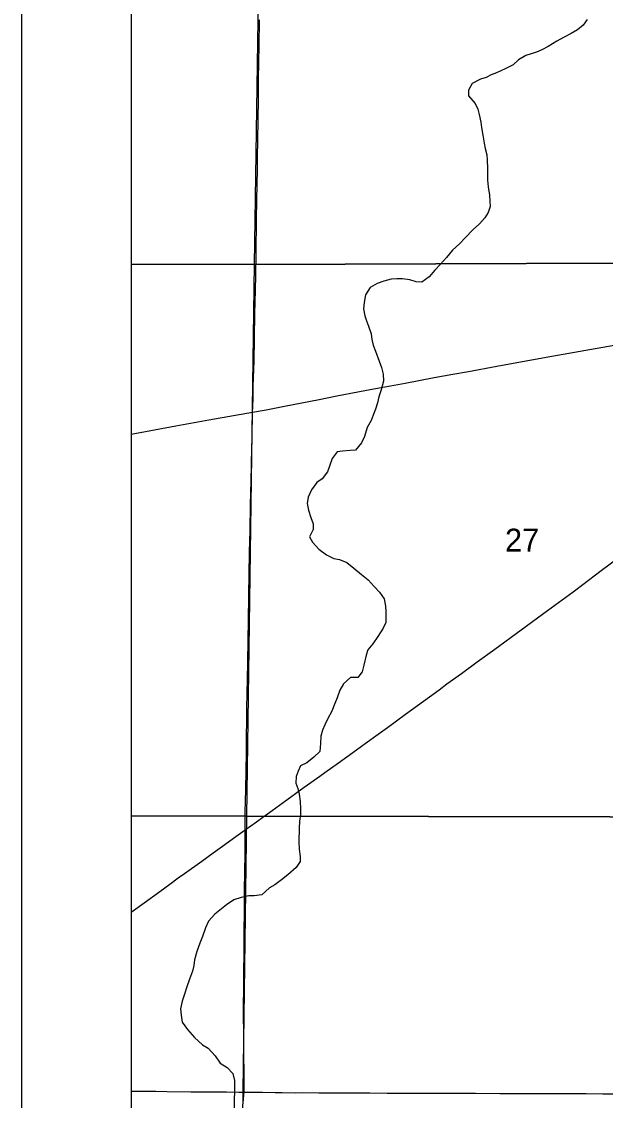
# Model space of a CAD drawing. Extents: x 0 to 34, y 0 to 22.
# Drawn here: x 2 to 2.532, y 14.978 to 15.961 of the extents above; entities that cross this region are included whole.
import ezdxf

# ---------------------------------------------------------------- set-up
doc = ezdxf.new("R2010")
doc.units = 0
for name, color, linetype in [('GM_X_Corporation', 7, 'Continuous'), ('GM_X_County_Road', 7, 'Continuous'), ('GM_X_Minor_River', 7, 'Continuous'), ('GM_X_Section_Text', 7, 'Continuous'), ('GM_X_Township_Road', 7, 'Continuous'), ('GM_X_US_Route', 7, 'Continuous'), ('SH_Data', 7, 'Continuous')]:
    doc.layers.add(name, color=color, linetype=linetype)

msp = doc.modelspace()

# ---------------------------------------------------------------- linework, layer by layer
at = {"layer": 'GM_X_Corporation'}
for points in [[(2.1, 20.71973), (2.1, 14.1), (8.9, 14.1), (8.9, 20.77204)], [(2.1, 17.73189), (2.1, 14.73602)]]:
    msp.add_lwpolyline(points, dxfattribs=at)
for points in [[(2.1, 16.24448), (2.1, 15.73976), (2.21216, 15.73952), (2.21995, 16.24572)], [(2.21995, 16.24572), (2.71086, 16.24467), (2.70763, 15.74147), (2.21216, 15.73952)], [(2.1, 15.73976), (2.1, 15.23741), (2.20515, 15.23711), (2.21216, 15.73952)], [(2.70763, 15.74147), (2.70155, 15.23601), (2.20515, 15.23711), (2.21216, 15.73952)], [(2.1, 15.23741), (2.1, 14.7363), (2.19853, 14.73564), (2.20515, 15.23711)], [(2.20515, 15.23711), (2.70155, 15.23601), (2.70022, 14.73337), (2.69643, 14.7334), (2.21255, 14.73573), (2.19853, 14.73564)]]:
    msp.add_lwpolyline(points, close=True, dxfattribs=at)
at = {"layer": 'GM_X_County_Road'}
for points in [[(2.20385, 15.22457), (2.21393, 15.23188), (2.21974, 15.23604), (2.22831, 15.24222), (2.23491, 15.24688), (2.23839, 15.24949), (2.25753, 15.2633), (2.27169, 15.27342), (2.27644, 15.27691), (2.2889, 15.28559), (2.30175, 15.29487), (2.30972, 15.30079), (2.31302, 15.30312), (2.32486, 15.31165), (2.33344, 15.31782), (2.34996, 15.32998), (2.36078, 15.33781), (2.37183, 15.34586), (2.38036, 15.35211), (2.38761, 15.35745), (2.40097, 15.36709), (2.41526, 15.37756), (2.43112, 15.38903), (2.4793, 15.42425), (2.50256, 15.4414), (2.51127, 15.44793), (2.52811, 15.46069), (2.54319, 15.47219)], [(2.1, 15.14939), (2.11167, 15.15801), (2.12594, 15.1685), (2.13502, 15.17502), (2.14282, 15.18067), (2.14834, 15.18471), (2.1643, 15.19604), (2.17461, 15.20353), (2.18319, 15.20969), (2.19531, 15.21839), (2.20385, 15.22457)], [(2.1, 14.98659), (2.10663, 14.98655), (2.12248, 14.98637), (2.13242, 14.98625), (2.15416, 14.986), (2.1868, 14.98575), (2.19798, 14.98562), (2.20275, 14.98559)], [(2.20275, 14.98559), (2.21104, 14.98554), (2.21943, 14.98547), (2.23122, 14.98527), (2.23743, 14.98517), (2.24955, 14.98507), (2.25638, 14.9851), (2.27099, 14.98505), (2.29119, 14.98505), (2.30456, 14.98495), (2.3173, 14.98487), (2.33314, 14.98463), (2.3434, 14.98465), (2.35303, 14.98462), (2.38815, 14.98462), (2.41364, 14.98451), (2.4357, 14.98438), (2.46492, 14.98446), (2.47797, 14.98431), (2.49195, 14.98433), (2.50159, 14.98436), (2.51433, 14.9843), (2.52955, 14.98417), (2.56374, 14.98414)]]:
    msp.add_lwpolyline(points, dxfattribs=at)
at = {"layer": 'GM_X_Minor_River'}
for points in [[(2.51541, 15.9629), (2.51158, 15.95762), (2.50643, 15.95348), (2.5009, 15.95011), (2.49367, 15.94656), (2.48776, 15.94319), (2.47975, 15.93812), (2.47404, 15.93513), (2.46909, 15.93308), (2.46434, 15.9316), (2.45939, 15.92993), (2.45273, 15.92618), (2.44795, 15.92166), (2.44052, 15.91773), (2.43272, 15.91419), (2.42796, 15.91251), (2.4232, 15.91008), (2.41807, 15.90841), (2.41064, 15.90448), (2.40718, 15.89844), (2.40733, 15.89312), (2.41316, 15.88625), (2.41559, 15.88111), (2.41707, 15.87616), (2.41854, 15.86932), (2.41908, 15.86457), (2.42016, 15.85755), (2.42144, 15.85014), (2.42235, 15.8452), (2.42402, 15.83949), (2.42436, 15.83456), (2.42469, 15.82696), (2.42465, 15.82184), (2.42442, 15.81653), (2.42513, 15.81026), (2.42622, 15.80266), (2.42656, 15.79735), (2.4269, 15.79241), (2.42516, 15.78711), (2.42209, 15.78201), (2.4173, 15.77674), (2.41157, 15.77147), (2.40431, 15.76393), (2.39896, 15.75847), (2.39265, 15.75263), (2.3871, 15.74584), (2.38175, 15.74), (2.37659, 15.73454), (2.37142, 15.72831), (2.36474, 15.72343), (2.35943, 15.72366), (2.35375, 15.7256), (2.34712, 15.7266), (2.34181, 15.72664), (2.33687, 15.72611), (2.33003, 15.72445), (2.32394, 15.72241), (2.31765, 15.71866), (2.31343, 15.71186), (2.31224, 15.70504), (2.31163, 15.69935), (2.31272, 15.69289), (2.31421, 15.68814), (2.31626, 15.68338), (2.31868, 15.67634), (2.31921, 15.67121), (2.3205, 15.66608), (2.32255, 15.66075), (2.3259, 15.65162), (2.32794, 15.64591), (2.32942, 15.63983), (2.32975, 15.63337), (2.3276, 15.62542), (2.32547, 15.61898), (2.32429, 15.61368), (2.32254, 15.60781), (2.32042, 15.60232), (2.31848, 15.59741), (2.31502, 15.59098), (2.3125, 15.58303), (2.3098, 15.57698), (2.30425, 15.57038), (2.2995, 15.57023), (2.29229, 15.56952), (2.28754, 15.56899), (2.28313, 15.56276), (2.28043, 15.55595), (2.27868, 15.55084)], [(2.27868, 15.55084), (2.27389, 15.54442), (2.26912, 15.54085), (2.26414, 15.53444), (2.26125, 15.52763), (2.26026, 15.52175), (2.26154, 15.51586), (2.26358, 15.50921), (2.26582, 15.50331), (2.26559, 15.49819), (2.26232, 15.49138), (2.26494, 15.48662), (2.27096, 15.48012), (2.27776, 15.47514), (2.28456, 15.47167), (2.28968, 15.47087), (2.29649, 15.46817), (2.3029, 15.46299), (2.30969, 15.45706), (2.31573, 15.45227), (2.32119, 15.44616), (2.32627, 15.44119), (2.3304, 15.4349), (2.33149, 15.42844), (2.33184, 15.42312), (2.33177, 15.41345), (2.32945, 15.40834), (2.32465, 15.40079), (2.32005, 15.39399), (2.31565, 15.38852), (2.31409, 15.3836), (2.31175, 15.37451), (2.31038, 15.36845), (2.30636, 15.36335), (2.29972, 15.36321), (2.29322, 15.35757), (2.28996, 15.3519), (2.28763, 15.34471), (2.28551, 15.3396), (2.28261, 15.33279), (2.27876, 15.32542), (2.27626, 15.32032), (2.27414, 15.31521), (2.27277, 15.30991), (2.27234, 15.30308), (2.27191, 15.29606), (2.26618, 15.29079), (2.25988, 15.28553), (2.25417, 15.28291), (2.25205, 15.278), (2.2503, 15.27307), (2.24988, 15.2672), (2.25174, 15.26225), (2.25284, 15.25712), (2.25375, 15.25047), (2.25427, 15.24382), (2.25423, 15.23851), (2.25324, 15.23245), (2.25281, 15.226), (2.25272, 15.21348), (2.25286, 15.20703), (2.25395, 15.20038), (2.25373, 15.19563), (2.25008, 15.19035), (2.24264, 15.18357), (2.23691, 15.17906), (2.23081, 15.17455), (2.22604, 15.17174), (2.21879, 15.16535), (2.21195, 15.16445), (2.20721, 15.1643), (2.19999, 15.16302), (2.19352, 15.16079), (2.18685, 15.1561), (2.18208, 15.15272), (2.17616, 15.14764), (2.17042, 15.14123), (2.16753, 15.13518), (2.16482, 15.12723), (2.16231, 15.12137), (2.1596, 15.1138), (2.15764, 15.10604), (2.15704, 15.10092), (2.15586, 15.0958), (2.15315, 15.08861), (2.15064, 15.08142), (2.14831, 15.0748), (2.14618, 15.06836), (2.1448, 15.06154), (2.14533, 15.05566), (2.14623, 15.04939), (2.1513, 15.04271), (2.1577, 15.03545), (2.16486, 15.02876), (2.16996, 15.02549), (2.17636, 15.01862), (2.18087, 15.01194), (2.18729, 15.00791), (2.19256, 15.00256), (2.19404, 14.99609), (2.19396, 14.98528)], [(2.19396, 14.98528), (2.19372, 14.9794), (2.19369, 14.9739), (2.19384, 14.96877), (2.1936, 14.96195), (2.19352, 14.95094), (2.1931, 14.94544), (2.19266, 14.93729), (2.19243, 14.93198), (2.19257, 14.92533), (2.19253, 14.91907), (2.19154, 14.91301), (2.18998, 14.9079), (2.18766, 14.90222), (2.18137, 14.89791), (2.17642, 14.89548), (2.17145, 14.89096), (2.16571, 14.88341), (2.15925, 14.88308), (2.15316, 14.87971), (2.14688, 14.87711), (2.14153, 14.87259), (2.13124, 14.86882)]]:
    msp.add_lwpolyline(points, dxfattribs=at)
at = {"layer": 'GM_X_Township_Road'}
for points in [[(2.21042, 15.60494), (2.21075, 15.61036), (2.21101, 15.6175), (2.21115, 15.62877), (2.21179, 15.65176), (2.21224, 15.67226), (2.21265, 15.69557), (2.21286, 15.70489), (2.21338, 15.72912), (2.21372, 15.74994), (2.21414, 15.78101), (2.21444, 15.7981), (2.21488, 15.82669), (2.215, 15.83663), (2.21544, 15.87081), (2.21574, 15.89101), (2.21603, 15.90872), (2.21641, 15.93897), (2.2167, 15.96248)], [(2.20385, 15.22457), (2.20383, 15.23293), (2.20387, 15.24071), (2.20412, 15.25097), (2.20433, 15.26091), (2.20456, 15.27894), (2.2048, 15.29448), (2.20499, 15.30691), (2.20519, 15.32649), (2.20532, 15.33519), (2.20556, 15.34917), (2.20579, 15.36191), (2.20604, 15.37714), (2.2064, 15.39765), (2.20669, 15.41505), (2.20711, 15.43805), (2.20782, 15.47721), (2.20806, 15.48778), (2.20828, 15.4971), (2.20871, 15.52072), (2.20915, 15.54216), (2.20946, 15.55708), (2.20986, 15.57262), (2.21009, 15.581), (2.21017, 15.58753), (2.21043, 15.59995), (2.21043, 15.60243), (2.21042, 15.60494)], [(2.20275, 14.98559), (2.20279, 14.98742), (2.20273, 14.99299), (2.2023, 15.06573), (2.20238, 15.07816), (2.20249, 15.09122), (2.20278, 15.11577), (2.2029, 15.12883), (2.20293, 15.13504), (2.20301, 15.14716), (2.20307, 15.15431), (2.2032, 15.17172), (2.20333, 15.18384), (2.20361, 15.20498), (2.20385, 15.22206), (2.20385, 15.22457)], [(2.20197, 14.97567), (2.2022, 14.97909), (2.20257, 14.98311), (2.20275, 14.98559)]]:
    msp.add_lwpolyline(points, dxfattribs=at)
at = {"layer": 'GM_X_US_Route'}
msp.add_lwpolyline([(2.1, 15.58507), (2.14052, 15.59252), (2.1705, 15.59794), (2.21042, 15.60494), (2.22282, 15.60723), (2.23959, 15.61056), (2.27102, 15.61662), (2.28565, 15.61955), (2.30794, 15.62376), (2.32259, 15.62653), (2.33603, 15.62906), (2.34946, 15.63163), (2.37603, 15.63662), (2.39285, 15.63967), (2.40725, 15.64215), (2.43293, 15.64686), (2.47788, 15.65503), (2.53998, 15.66623)], dxfattribs=at)
at = {"layer": 'SH_Data'}
for p, q in [((2, 21), (2, 14)), ((2.1, 20.9), (2.1, 14.1))]:
    msp.add_line(p, q, dxfattribs=at)

# ---------------------------------------------------------------- texts
at = {"layer": 'GM_X_Section_Text'}
msp.add_text('27', height=0.020928, rotation=0.00001, dxfattribs=at).set_placement((2.44049, 15.478))

doc.saveas('drawing.dxf')
